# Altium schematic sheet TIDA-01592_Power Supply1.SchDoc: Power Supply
size 431 x 279 mm; Date: Not shown in title block; ApprovedBy: Not shown in title block; CheckedBy: Not shown in title block; Author: Not shown in title block; CompanyName: Not shown in title block; DrawnBy: Abhishek Vishwa; Engineer: Abhishek Vishwa; Organization: Not shown in title block; Address1: Not shown in title block; Address2: Not shown in title block; Address3: Not shown in title block; Address4: Not shown in title block; DocumentNumber: 1; Revision: Use project parameter SCH_Rev; SheetNumber: 2; SheetTotal: 5; PageSetup: Record=PageOptions¦CenterHorizontal=True¦CenterVertical=True¦PrintScale=1.00¦XCorrection=1.00¦YCorrection=1.00¦PrintKind=0¦BorderSize=5000000¦LeftOffset=0¦BottomOffset=0¦Orientation=2¦PaperLength=1000¦PaperWidth=1000¦Scale=100¦PaperSource=15¦PrintQuality=600¦MediaType=1¦DitherType=10¦PaperKind=Letter¦PrintScaleMode=1
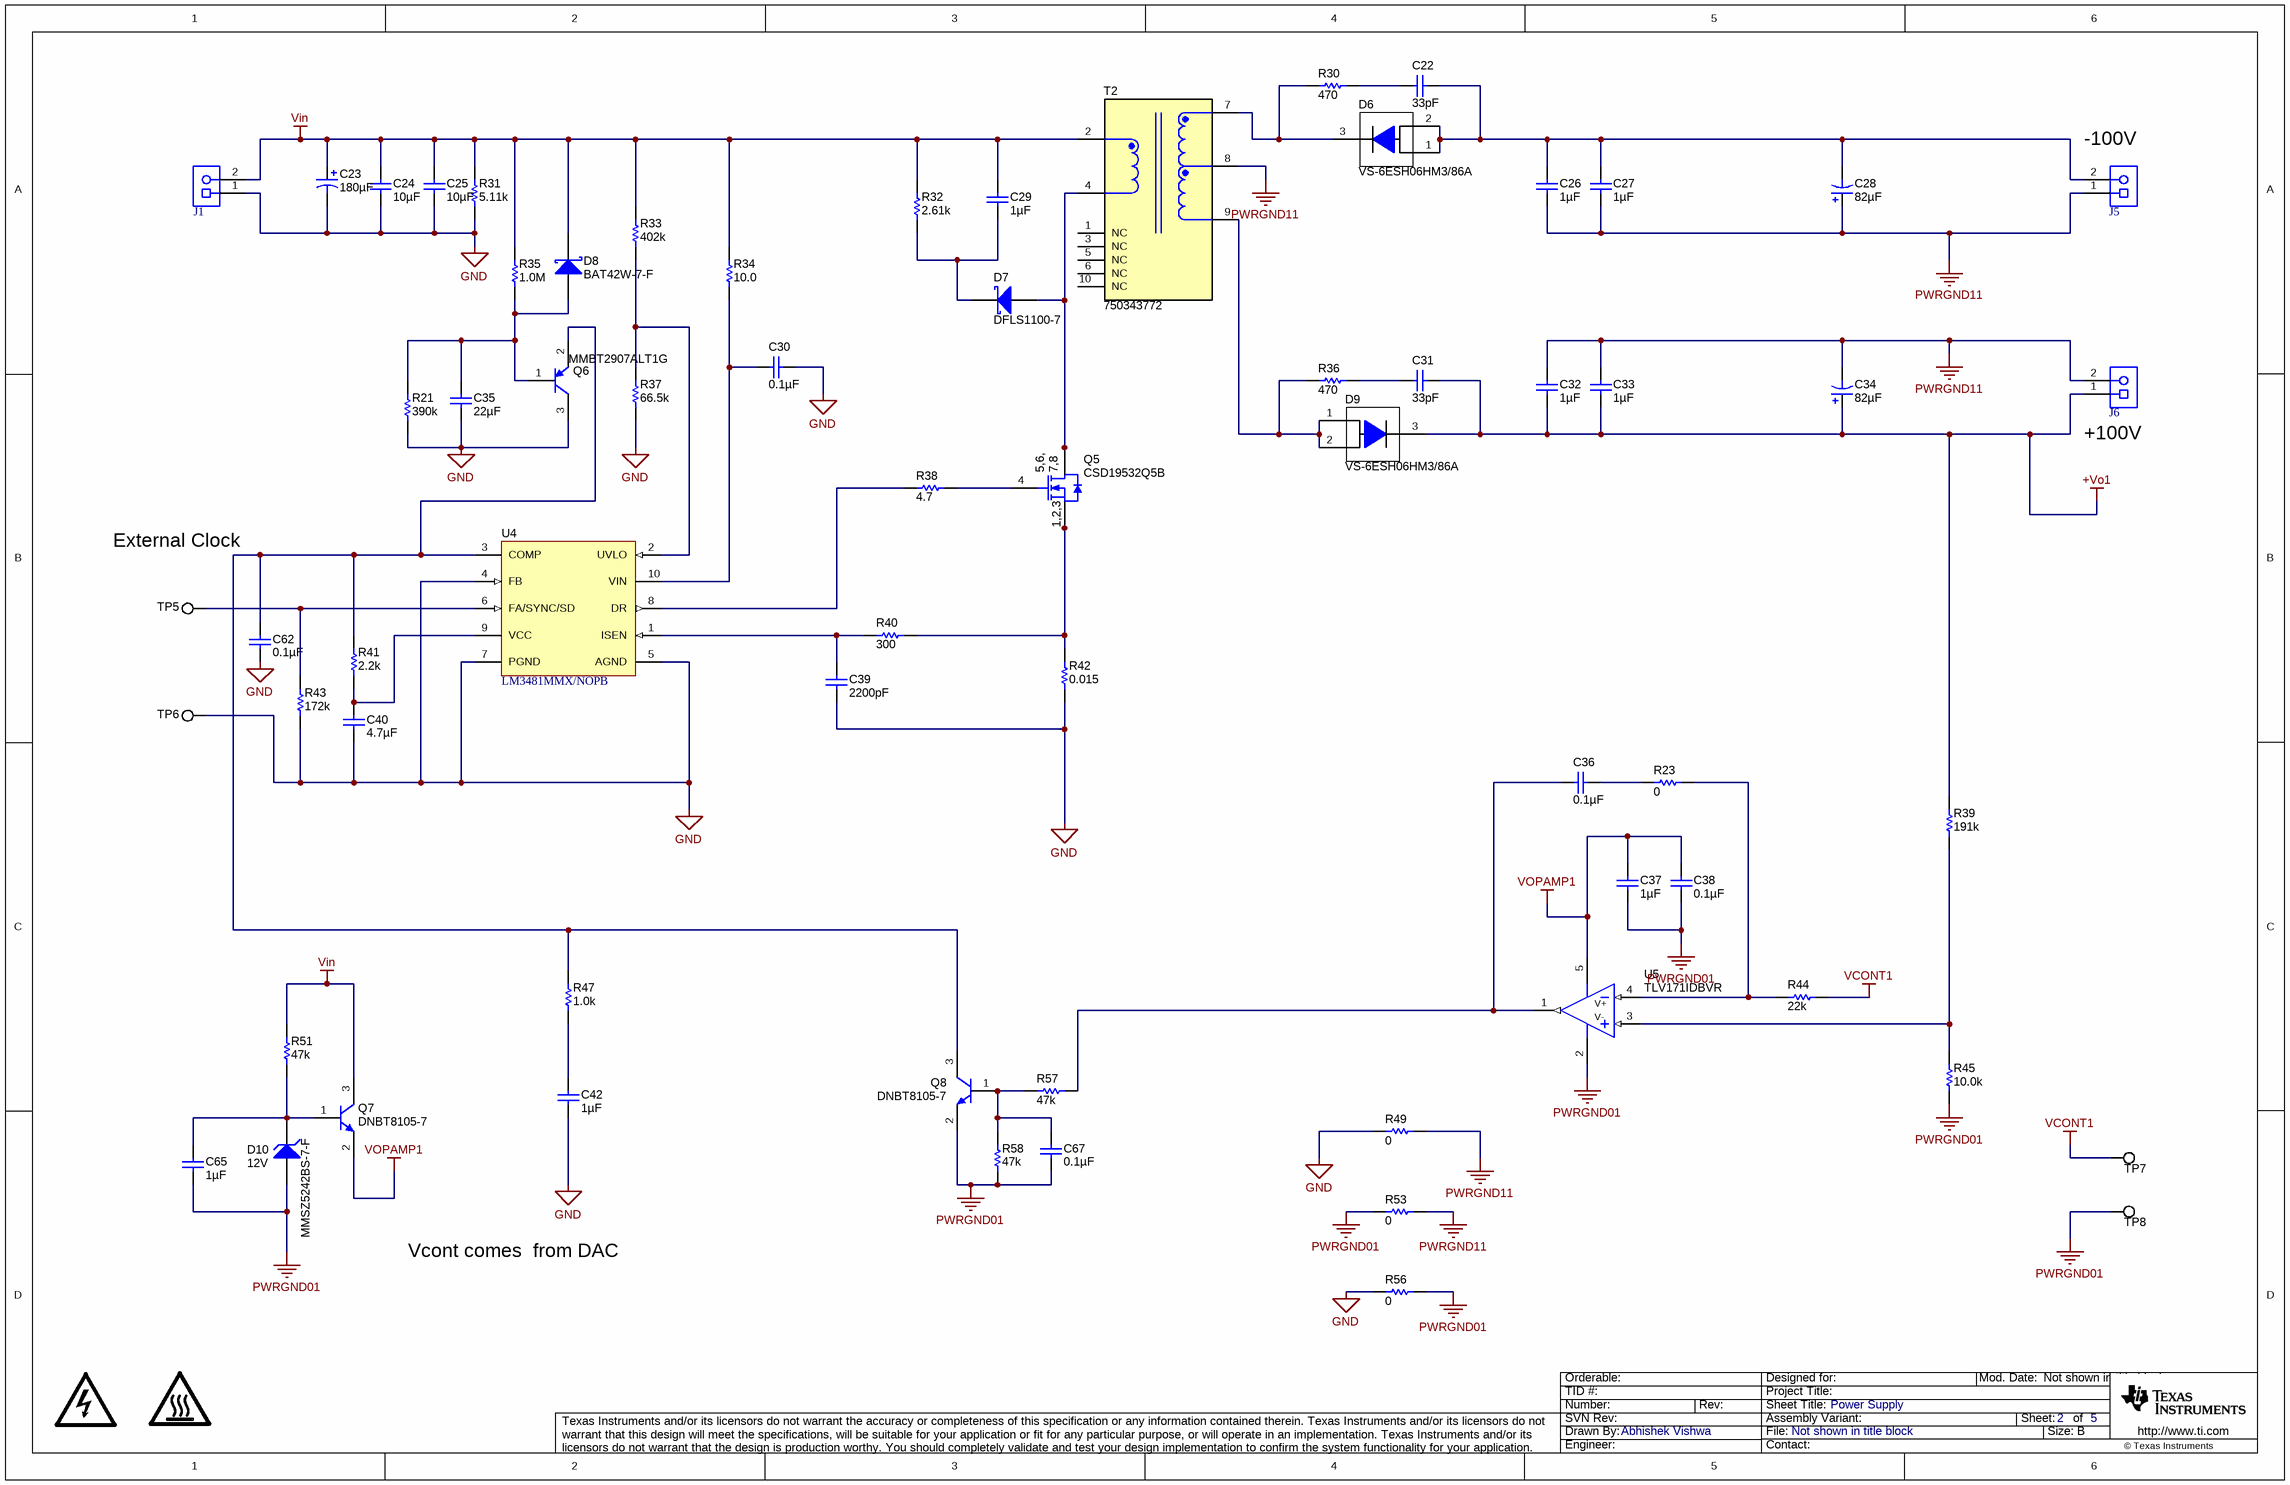
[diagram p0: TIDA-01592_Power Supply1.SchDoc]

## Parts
C22  ValueDisplayed: 33pF  [1206]  (hidden comment: 12067A330JAT2A)
C23  ValueDisplayed: 180µF  [FC_630x1120]  (hidden comment: 35TXW180MEFC6.3X25)
C24  ValueDisplayed: 10µF  [1206_180]  (hidden comment: GRM31CR61H106KA12L)
C25  ValueDisplayed: 10µF  [1206_180]  (hidden comment: GRM31CR61H106KA12L)
C26  ValueDisplayed: 1µF  [1812_180]  (hidden comment: C4532X7T2E105M250KE)
C27  ValueDisplayed: 1µF  [1812_180]  (hidden comment: C4532X7T2E105M250KE)
C28  ValueDisplayed: 82µF  [NHG_1000x2000]  (hidden comment: UCY2C820MPD9)
C29  ValueDisplayed: 1µF  [1206_180]  (hidden comment: GRM31CR72A105KA01L)
C30  ValueDisplayed: 0.1µF  [0603]  (hidden comment: GRM188R71H104KA93D)
C31  ValueDisplayed: 33pF  [1206]  (hidden comment: 12067A330JAT2A)
C32  ValueDisplayed: 1µF  [1812_180]  (hidden comment: C4532X7T2E105M250KE)
C33  ValueDisplayed: 1µF  [1812_180]  (hidden comment: C4532X7T2E105M250KE)
C34  ValueDisplayed: 82µF  [NHG_1000x2000]  (hidden comment: UCY2C820MPD9)
C35  ValueDisplayed: 22µF  [0805_HV1]  (hidden comment: C2012X5R1V226M125AC)
C36  ValueDisplayed: 0.1µF  [0603]  (hidden comment: GRM188R71H104KA93D)
C37  ValueDisplayed: 1µF  [0603]  (hidden comment: UMK107AB7105KA-T)
C38  ValueDisplayed: 0.1µF  [0603]  (hidden comment: GRM188R71H104KA93D)
C39  ValueDisplayed: 2200pF  [0402]  (hidden comment: GRM155R61H222KA01D)
C40  ValueDisplayed: 4.7µF  [0603]  (hidden comment: 0603ZD475KAT2A)
C42  ValueDisplayed: 1µF  [0603]  (hidden comment: C0603C105K3RACTU)
C62  ValueDisplayed: 0.1µF  [0603]  (hidden comment: GRM188R71H104KA93D)
C65  ValueDisplayed: 1µF  [0603]  (hidden comment: C0603C105K3RACTU)
C67  ValueDisplayed: 0.1µF  [0603]  (hidden comment: GRM188R71H104KA93D)
D6  VS-6ESH06HM3/86A  [TO-277A]
D7  DFLS1100-7  [PowerDI123]
D8  BAT42W-7-F  [SOD-123]
D9  VS-6ESH06HM3/86A  [TO-277A]
D10  MMSZ5242BS-7-F  value 12V  [SOD-323]
J1  1727010  [PhoenixConact_1727010]  (value not drawn)
J5  1727010  [PhoenixConact_1727010]  (value not drawn)
J6  1727010  [PhoenixConact_1727010]  (value not drawn)
LOGO2  CAUTION HOT SURFACE  [IEC_HotSurface_Small]  (value not drawn)  (graphical)
LOGO8  DANGER HIGH VOLTAGE  [IEC_HighVoltage_Small]  (value not drawn)  (graphical)
Q5  CSD19532Q5B  [DNK0008A]
Q6  MMBT2907ALT1G  [SOT-23]
Q7  DNBT8105-7  [SOT-23]
Q8  DNBT8105-7  [SOT-23]
R21  ValueDisplayed: 390k  [0603]  (hidden comment: CRCW0603390KJNEA)
R23  ValueDisplayed: 0  [0402]  (hidden comment: CRCW04020000Z0ED)
R30  ValueDisplayed: 470  [1206]  (hidden comment: CRCW1206470RJNEA)
R31  ValueDisplayed: 5.11k  [TNPW0603]  (hidden comment: TNPW06035K11BEEA)
R32  ValueDisplayed: 2.61k  [2010]  (hidden comment: CRCW20102K61FKEF)
R33  ValueDisplayed: 402k  [0603]  (hidden comment: CRCW0603402KFKEA)
R34  R4: 10.0  [0603]  (hidden comment: CRCW060310R0FKEAHP)
R35  ValueDisplayed: 1.0M  [0603]  (hidden comment: CRCW06031M00JNEA)
R36  ValueDisplayed: 470  [1206]  (hidden comment: CRCW1206470RJNEA)
R37  ValueDisplayed: 66.5k  [0603]  (hidden comment: CRCW060366K5FKEA)
R38  ValueDisplayed: 4.7  [0603]  (hidden comment: CRCW06034R70JNEA)
R39  ValueDisplayed: 191k  [0603]  (hidden comment: CRCW0603191KFKEA)
R40  ValueDisplayed: 300  [0603]  (hidden comment: CRCW0603300RJNEA)
R41  ValueDisplayed: 2.2k  [0603]  (hidden comment: ERJ-3GEYJ222V)
R42  ValueDisplayed: 0.015  [2010]  (hidden comment: WSL2010R0150FEA18)
R43  ValueDisplayed: 172k  [0603]  (hidden comment: RT0603DRE07172KL)
R44  ValueDisplayed: 22k  [0603]  (hidden comment: CRCW060322K0JNEA)
R45  ValueDisplayed: 10.0k  [0603]  (hidden comment: CRCW060310K0FKEA)
R47  ValueDisplayed: 1.0k  [0603]  (hidden comment: CRCW06031K00JNEA)
R49  ValueDisplayed: 0  [2010L]  (hidden comment: CRCW20100000Z0EF)
R51  ValueDisplayed: 47k  [1206]  (hidden comment: CRCW120647K0JNEA)
R53  ValueDisplayed: 0  [2010L]  (hidden comment: CRCW20100000Z0EF)
R56  ValueDisplayed: 0  [2010L]  (hidden comment: CRCW20100000Z0EF)
R57  ValueDisplayed: 47k  [0603]  (hidden comment: RC0603JR-0747KL)
R58  ValueDisplayed: 47k  [0603]  (hidden comment: RC0603JR-0747KL)
T2  750343772  [Wurth_EE16_7_5_5278]
TP5  5002  [Keystone5002]  (value not drawn)
TP6  5002  [Keystone5002]  (value not drawn)
TP7  5002  [Keystone5002]  (value not drawn)
TP8  5002  [Keystone5002]  (value not drawn)
U4  LM3481MMX/NOPB  [MUB10A_N]
U5  TLV171IDBVR  [DBV0005A_N]

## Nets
+Vo1: C31.1 C32.2 C33.2 C34.1(+) D9.3(K) J6.1 R39.2
GND: C23.2(-) C24.2 C25.2 C30.1 C35.2 C39.2 C40.2 C42.2 C62.1 J1.1 Q6.3(C) R21.1 R31.1 R37.1 R42.1 R43.1 R49.1 R56.1 TP6.1 U4.4(FB) U4.5(AGND) U4.7(PGND)
PWRGND01: C37.2 C38.2 C65.2 C67.1 D10.2(A) Q8.2(E) R45.2 R53.1 R56.2 R58.2 TP8.1 U5.2(V-)
PWRGND11: C26.2 C27.2 C28.1(+) C32.1 C33.1 C34.2(-) J5.1 J6.2 R49.2 R53.2 T2.8
VCONT1: R44.2 TP7.1
Vin: C23.1(+) C24.1 C25.1 C29.1 D8.1(K) J1.2 Q7.3(C) R31.2 R32.2 R33.2 R34.1 R35.2 R51.2 T2.2
VOPAMP1: C37.1 C38.1 Q7.2(E) U5.5(V+)
NetC22_1: C22.1 C26.1 C27.1 C28.2(-) D6.1(A) D6.2(A) J5.2
NetC22_2: C22.2 R30.2
NetC29_2: C29.2 D7.1(K) R32.1
NetC30_2: C30.2 R34.2 U4.10(VIN)
NetC31_2: C31.2 R36.2
NetC35_1: C35.1 D8.2(A) Q6.1(B) R21.2 R35.1
NetC36_1: C36.1 R57.1 U5.1(OUT)
NetC36_2: C36.2 R23.1
NetC39_1: C39.1 R40.1 U4.1(ISEN)
NetC40_1: C40.1 R41.2 U4.9(VCC)
NetC42_1: C42.1 R47.1
NetC62_2: C62.2 Q6.2(E) Q8.3(C) R41.1 R47.2 U4.3(COMP)
NetC65_1: C65.1 D10.1(K) Q7.1(B) R51.1
NetC67_2: C67.2 Q8.1(B) R57.2 R58.1
NetD6_3: D6.3(K) R30.1 T2.7
NetD7_2: D7.2(A) Q5.5(D) Q5.6(D) Q5.7(D) Q5.8(D) Q5.9(D) T2.4
NetD9_1: D9.1(A) D9.2(A) R36.1 T2.9
NetQ5_1: Q5.1(S) Q5.2(S) Q5.3(S) R40.2 R42.2
NetQ5_4: Q5.4(G) R38.2
NetR23_2: R23.2 R44.1 U5.4(IN-)
NetR33_1: R33.1 R37.2 U4.2(UVLO)
NetR38_1: R38.1 U4.8(DR)
NetR39_1: R39.1 R45.1 U5.3(IN+)
NetR43_2: R43.2 TP5.1 U4.6(FA/SYNC/SD)

Not connected (* = marked no-connect by the designer): T2 1(NC) 3(NC) 5(NC) 6(NC) 10(NC)

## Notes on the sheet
- (near J5) -100V
- (near J6) +100V
- External Clock Synchronization
- Vcont comes  from DAC

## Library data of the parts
C22 C31 = 12067A330JAT2A: CAP, CERM, 33 pF, 500 V,+/- 5%, C0G/NP0, 1206; Manufacturer: AVX; Polarized: N; CompType: Capacitor; Value: 33pF; U/M: EA; Cap_F: 0.000000000033; Tolerance_%: 5; VDC_V: 500; Value2: 500V; TaMin_C: -55; TaMax_C: 125; SizeArea_mm2: 5.12; SizeAreaWB_mm2: 10.92; SizeX_mm: 3.2; SizeY_mm: 1.6; SizeZ_mm: 1.35; AEC Category: Q200; Green_Lifecycle: Not Set; Green_REACh: Incomplete
C23 = EEU-FC1V470: CAP, AL, 180 µF, 35 V, +/- 20%, TH; Manufacturer: Rubycon; Polarized: Y; CompType: Capacitor; Value: 180uF; U/M: EA; Cap_F: 0.000180; Tolerance_%: 20; VDC_V: 35; Value2: 35V; IRMS_A: 0.29; TaMin_C: -55; TaMax_C: 105; Cap_Case: 6.3x11.2mm; SizeAreaWB_mm2: 68.89; SizeArea_mm2: 39.69; SizeX_mm: 6.3; SizeZ_mm: 12.2; AEC Category: Q200; AEC Grade: 2
C24 C25 = GRM31CR61H106KA12L: CAP, CERM, 10 µF, 50 V,+/- 10%, X5R, 1206; Manufacturer: MuRata; Polarized: N; CompType: Capacitor; Value: 10uF; U/M: EA; Cap_F: 0.00001; Tolerance_%: 10; VDC_V: 50; Value2: 50V; TaMin_C: -55; TaMax_C: 85; Cap_Case: 1206; SizeArea_mm2: 5.12; SizeAreaWB_mm2: 10.92; SizeX_mm: 3.2; SizeY_mm: 1.6; SizeZ_mm: 1.8; AEC Category: Q200; Green_Lifecycle: Active; Green_REACh: Passed
C26 C27 C32 C33 = C4532X7R1H105K160KA: CAP, CERM, 1 µF, 250 V,+/- 20%, X7T, 1812; Manufacturer: TDK Corporation; Polarized: N; CompType: Capacitor; Value: 1uF; U/M: EA; Cap_F: 0.000001; Tolerance_%: 20; ESR_ohm: 0.007217; Value1: 0.007217 ohm; VDC_V: 50; Value2: 250V; IRMS_A: 2.85919; TaMin_C: -55; TaMax_C: 125; Cap_Case: 1812; SizeArea_mm2: 14.4; SizeAreaWB_mm2: 23.1; SizeX_mm: 4.5; SizeY_mm: 3.2; SizeZ_mm: 1.8; AEC Category: Q200
C28 C34 = ECA-2AHG101: CAP, AL, 82 µF, 160 V, +/- 20%, TH; Manufacturer: Nichicon; Polarized: Y; CompType: Capacitor; Value: 82uF; U/M: EA; Cap_F: 0.0001; Tolerance_%: 20; VDC_V: 160; Value2: 160V; IRMS_A: 0.265; TaMin_C: -55; TaMax_C: 105; Cap_Case: 10x20mm; SizeAreaWB_mm2: 144; SizeArea_mm2: 100; SizeX_mm: 10; SizeZ_mm: 22; AEC Category: Q200; Green_Lifecycle: Active; Green_REACh: Passed
C29 = GRM31CR72A105KA01L: CAP, CERM, 1 µF, 100 V,+/- 10%, X7R, 1206; Manufacturer: MuRata; Polarized: N; CompType: Capacitor; Value: 1uF; U/M: EA; Cap_F: 0.000001; Tolerance_%: 10; VDC_V: 100; Value2: 100V; TaMin_C: -55; TaMax_C: 125; Cap_Case: 1206; SizeArea_mm2: 5.12; SizeAreaWB_mm2: 10.92; SizeX_mm: 3.2; SizeY_mm: 1.6; SizeZ_mm: 1.8; AEC Category: Q200; Green_Lifecycle: Active; Green_REACh: Passed
C30 C36 C38 C62 C67 = GRM188R71H104KA93D: CAP, CERM, 0.1 µF, 50 V,+/- 10%, X7R, 0603; Manufacturer: MuRata; Polarized: N; CompType: Capacitor; Value: 0.1uF; U/M: EA; Cap_F: 0.0000001; Tolerance_%: 10; VDC_V: 50; Value2: 50V; TaMin_C: -55; TaMax_C: 125; SizeArea_mm2: 1.28; SizeAreaWB_mm2: 4.68; SizeX_mm: 1.6; SizeY_mm: 0.8; SizeZ_mm: 1; AEC Category: Q200; Green_Lifecycle: Active; Green_REACh: Passed
C35 = GRM21BC81C226ME44L: CAP, CERM, 22 µF, 35 V,+/- 20%, X5R, 0805; Manufacturer: TDK Corporation; Polarized: N; CompType: Capacitor; Value: 22uF; U/M: EA; Cap_F: 0.000022; Tolerance_%: 20; VDC_V: 16; Value2: 35V; TempCo: X6S; TaMin_C: -55; TaMax_C: 105; Cap_Case: 0805; SizeArea_mm2: 2.5; SizeAreaWB_mm2: 6.75; SizeX_mm: 2; SizeY_mm: 1.25; SizeZ_mm: 1.45; AEC Category: Q200
C37 = UMK107AB7105KA-T: CAP, CERM, 1 µF, 50 V,+/- 10%, X7R, 0603; Manufacturer: Taiyo Yuden; Polarized: N; CompType: Capacitor; Value: 1uF; U/M: EA; Cap_F: 0.000001; Tolerance_%: 10; VDC_V: 50; Value2: 50V; TaMin_C: -55; TaMax_C: 125; SizeArea_mm2: 1.28; SizeAreaWB_mm2: 4.68; SizeX_mm: 1.6; SizeY_mm: 0.8; SizeZ_mm: 1; AEC Category: Q200; Green_Lifecycle: Active; Green_REACh: Passed
C39 = GRM155R61H222KA01D: CAP, CERM, 2200 pF, 50 V,+/- 10%, X5R, 0402; Manufacturer: MuRata; Polarized: N; CompType: Capacitor; Value: 2200pF; U/M: EA; Cap_F: 0.0000000022; Tolerance_%: 10; VDC_V: 50; Value2: 50V; TaMin_C: -55; TaMax_C: 85; SizeArea_mm2: 0.5; SizeAreaWB_mm2: 3; SizeX_mm: 1; SizeZ_mm: 0.6; AEC Category: Q200; Green_Lifecycle: Active; Green_REACh: Passed
C40 = 0603ZD475KAT2A: CAP, CERM, 4.7 µF, 10 V,+/- 10%, X5R, 0603; Manufacturer: AVX; Polarized: N; CompType: Capacitor; Value: 4.7uF; U/M: EA; Cap_F: 0.0000047; Tolerance_%: 10; Value2: 10V; TaMin_C: -55; TaMax_C: 85; SizeArea_mm2: 1.28; SizeAreaWB_mm2: 4.68; SizeX_mm: 1.6; SizeY_mm: 0.8; SizeZ_mm: 1; AEC Category: Q200; Green_Lifecycle: Active; Green_REACh: Passed
C42 C65 = C0603C105K3RACTU: CAP, CERM, 1 µF, 25 V,+/- 10%, X7R, 0603; Manufacturer: Kemet; Polarized: N; CompType: Capacitor; Value: 1uF; U/M: EA; Cap_F: 0.000001; Tolerance_%: 10; VDC_V: 25; Value2: 25V; TaMin_C: -55; TaMax_C: 125; SizeArea_mm2: 1.28; SizeAreaWB_mm2: 4.68; SizeX_mm: 1.6; SizeY_mm: 0.8; SizeZ_mm: 1; AEC Category: Q200; Green_Lifecycle: Active; Green_REACh: Passed
D6 D9 = VS-6ESH06HM3/86A: Diode, Hyperfast, 600 V, 6 A, AEC-Q101, TO-277A; Manufacturer: Vishay-Semiconductor; SymbolCreator: a0412235; U/M: EA; Vf_V: 1.05; Value: 600V; Value1: 6A; Value2: 1.05V; Io_A: 6; Vr_V: 600; TJmax_C: 175; RJC_CperW: 3.5; SizeAreaWB_mm2: 57.375; SizeArea_mm2: 30.875; SizeX_mm: 6.5; SizeY_mm: 4.75; SizeZ_mm: 1.2; AEC Category: Q101; AEC Qualified: Y
D7 = DFLS1100-7: Diode, Schottky, 100 V, 1 A, PowerDI123; Manufacturer: Diodes Inc.; U/M: EA; Vf_V: 0.77; Value: 100V; Value1: 1A; Value2: 0.77V; Io_A: 1; Vr_V: 100; TJmax_C: 175; RJC_CperW: 7; SizeAreaWB_mm2: 13.066; SizeArea_mm2: 6.586; SizeX_mm: 3.7; SizeY_mm: 1.78; SizeZ_mm: 0.98; AEC Category: Q101; Green_Lifecycle: Active; Green_REACh: Passed
D8 = BAT42W-7-F: Diode, Schottky, 30 V, 0.2 A, SOD-123; Manufacturer: Diodes Inc.; U/M: EA; Vf_V: 1; Value: 30V; Value1: 0.2A; Value2: 1V; Io_A: 0.2; Vr_V: 30; SizeAreaWB_mm2: 13.095; SizeArea_mm2: 6.545; SizeX_mm: 3.85; SizeY_mm: 1.7; SizeZ_mm: 1.35; AEC Category: Q101; Green_Lifecycle: Not Set; Green_REACh: Incomplete
D10 = MMSZ5242BS-7-F: Diode, Zener, 12 V, 200 mW, SOD-323; Manufacturer: Diodes Inc.; SymbolCreator: a0412235; U/M: EA; Power_W: 0.2; Vz_V: 12; Value1: 0.2W; RJA_CperW: 350; SizeAreaWB_mm2: 8.695; SizeArea_mm2: 3.645; SizeX_mm: 2.7; SizeY_mm: 1.35; SizeZ_mm: 1; AEC Category: Q101
J1 J5 J6 = 1727010: Conn Term Block, 2POS, 3.81mm, TH; Manufacturer: Phoenix Contact; SymbolCreator: a0412235; CompType: Terminal Block
LOGO2 = IEC_HotSurface: IEC 61010-1 Hot Surface Warning; SymbolCreator: a0412235
LOGO8 = IEC_HighVoltage: IEC 61010-1 High Voltage Warning; SymbolCreator: a0412235
Q5 = CSD19532Q5B: MOSFET, N-CH, 100 V, 17 A, DNK0008A (VSON-CLIP-8); Manufacturer: Texas Instruments; Alternate Manufacturer: None; U/M: EA; ChType: N; Value: 100V; VdsMax_V: 100; Value1: ? ohm; Value2: 48 nC; QgTyp_nC: 48; Vgs_V: 20; IdsMax_A: 17; SizeAreaWB_mm2: 56; SizeArea_mm2: 30; SizeX_mm: 6; SizeY_mm: 5; SizeZ_mm: 1; AEC Category: Q101
Q6 = MMBT2907ALT1G, ON Semiconductor: Transistor, PNP, 60 V, 0.6 A, SOT-23; CompType: BJT; PNP: 1; NPN: 0; Vceo_V: 60; Vcesat1_V: 1.6; Value: 60 V; IcRated_A: 0.6; Value1: 0.6 A; TaMin_C: -55; TaMax_C: 150; SizeAreaWB_mm2: 14; SizeArea_mm2: 7.5; SizeX_mm: 2.5; SizeY_mm: 3; SizeZ_mm: 1.1; U/M: EA; AEC Category: Q101; Green_Lifecycle: Active; Green_REACh: Passed
Q7 Q8 = DNBT8105-7, Diodes Inc.: Transistor, NPN, 60 V, 1 A, AEC-Q101, SOT-23; CompType: BJT; PNP: 0; NPN: 1; Vceo_V: 60; Vcesat1_V: 0.25; Value: 60 V; Value1: 1 A; HfeMax: 300; TaMin_C: -55; TaMax_C: 150; SizeAreaWB_mm2: 14; SizeArea_mm2: 7.5; SizeX_mm: 2.5; SizeY_mm: 3; SizeZ_mm: 1.1; U/M: EA; AEC Category: Q101; AEC Qualified: Y; Green_Lifecycle: Not Set; Green_REACh: Incomplete
R21 = CRCW0603390KJNEA: RES, 390 k, 5%, 0.1 W, 0603; Manufacturer: Vishay-Dale; CompType: Resistor; Value: 390k; Res_ohm: 390000; Tolerance_%: 5; Power_W: 0.1; Value2: 0.1W; VDC_V: 75; TempCo: 200 ppm/C; SizeArea_mm2: 1.28; SizeX_mm: 1.6; SizeY_mm: 0.8; SizeZ_mm: 1; EIA_Code: E24; U/M: EA; AEC Category: Q200
R23 = CRCW04020000Z0ED: RES, 0, 5%, 0.063 W, 0402; Manufacturer: Vishay-Dale; CompType: Resistor; Value: 0; Value_Code: 0000; Tolerance_%: 5; Power_W: 0.063; Value2: 0.063W; VDC_V: 50; TempCo: 200 ppm/C; SizeArea_mm2: 0.5; SizeX_mm: 1; SizeZ_mm: 0.6; EIA_Code: E24; U/M: EA; AEC Category: Q200; Green_Lifecycle: Active; Green_REACh: Passed
R30 R36 = CRCW1206470RJNEA: RES, 470, 5%, 0.25 W, 1206; Manufacturer: Vishay-Dale; CompType: Resistor; Value: 470; Value_Code: 470R; Tolerance_%: 5; Power_W: 0.25; Value2: 0.25W; VDC_V: 200; TempCo: 200 ppm/C; SizeArea_mm2: 5.12; SizeX_mm: 3.2; SizeY_mm: 1.6; SizeZ_mm: 1.35; EIA_Code: E24; U/M: EA; AEC Category: Q200
R31 = TNPW06035K11BEEA: RES, 5.11 k, 0.1%, 0.1 W, AEC-Q200 Grade 1, 0603; Manufacturer: Vishay-Dale; CompType: Resistor; Value: 5.11k; Res_ohm: 5110; Value_Code: 5k11; Tolerance_%: 0.1; Value2: 0.1W; VDC_V: 75; TempCo: 25 ppm/C; SizeArea_mm2: 1.36; SizeX_mm: 1.6; SizeY_mm: 0.85; SizeZ_mm: 0.55; EIA_Code: E192; U/M: EA; AEC Category: Q200; AEC Qualified: Y; AEC Grade: 1
R32 = CRCW20102K61FKEF: RES, 2.61 k, 1%, 0.75 W, AEC-Q200 Grade 0, 2010; Manufacturer: Vishay-Dale; CompType: Resistor; Value: 2.61k; Res_ohm: 2610; Value_Code: 2k61; Tolerance_%: 1; Power_W: 0.75; Value2: 0.75W; VDC_V: 400; TempCo: 100 ppm/C; SizeArea_mm2: 12.5; SizeX_mm: 5; SizeY_mm: 2.5; SizeZ_mm: 1.66; EIA_Code: E96; U/M: EA; AEC Category: Q200; AEC Qualified: Y; AEC Grade: 0
R33 = CRCW0603402KFKEA: RES, 402 k, 1%, 0.1 W, 0603; Manufacturer: Vishay-Dale; CompType: Resistor; Value: 402k; Res_ohm: 402000; Tolerance_%: 1; Power_W: 0.1; Value2: 0.1W; VDC_V: 75; TempCo: 100 ppm/C; SizeArea_mm2: 1.28; SizeX_mm: 1.6; SizeY_mm: 0.8; EIA_Code: E96; U/M: EA; AEC Category: Q200; Green_Lifecycle: Active; Green_REACh: Passed
R34 = CRCW060310R0FKEAHP: RES, 10.0, 1%, 0.25 W, 0603; Manufacturer: Vishay-Dale; CompType: Resistor; Value: 10.0; Res_ohm: 10; Value_Code: 10R0; Tolerance_%: 1; Power_W: 0.25; Value2: 0.25W; VDC_V: 75; TempCo: 100 ppm/C; SizeArea_mm2: 1.28; SizeX_mm: 1.6; SizeY_mm: 0.8; EIA_Code: E96; U/M: EA; AEC Category: Q200; Green_Lifecycle: Active; Green_REACh: Passed
R35 = CRCW06031M00JNEA: RES, 1.0 M, 5%, 0.1 W, 0603; Manufacturer: Vishay-Dale; CompType: Resistor; Value: 1.0Meg; Res_ohm: 1000000; Value_Code: 1M00; Tolerance_%: 5; Power_W: 0.1; Value2: 0.1W; VDC_V: 75; TempCo: 200 ppm/C; SizeArea_mm2: 1.28; SizeX_mm: 1.6; SizeY_mm: 0.8; SizeZ_mm: 1; EIA_Code: E24; U/M: EA; AEC Category: Q200; Green_Lifecycle: Active; Green_REACh: Passed
R37 = CRCW060366K5FKEA: RES, 66.5 k, 1%, 0.1 W, 0603; Manufacturer: Vishay-Dale; CompType: Resistor; Value: 66.5k; Res_ohm: 66500; Value_Code: 66k5; Tolerance_%: 1; Power_W: 0.1; Value2: 0.1W; VDC_V: 75; TempCo: 100 ppm/C; SizeArea_mm2: 1.28; SizeX_mm: 1.6; SizeY_mm: 0.8; EIA_Code: E96; U/M: EA; AEC Category: Q200; Green_Lifecycle: Active; Green_REACh: Passed
R38 = CRCW06034R70JNEA: RES, 4.7, 5%, 0.1 W, 0603; Manufacturer: Vishay-Dale; CompType: Resistor; Value: 4.7; Value_Code: 4R70; Tolerance_%: 5; Power_W: 0.1; Value2: 0.1W; VDC_V: 75; TempCo: 200 ppm/C; SizeArea_mm2: 1.28; SizeX_mm: 1.6; SizeY_mm: 0.8; SizeZ_mm: 1; EIA_Code: E24; U/M: EA; AEC Category: Q200; Green_Lifecycle: Active; Green_REACh: Passed
R39 = CRCW0603191KFKEA: RES, 191 k, 1%, 0.1 W, 0603; Manufacturer: Vishay-Dale; CompType: Resistor; Value: 191k; Res_ohm: 191000; Tolerance_%: 1; Power_W: 0.1; Value2: 0.1W; VDC_V: 75; TempCo: 100 ppm/C; SizeArea_mm2: 1.28; SizeX_mm: 1.6; SizeY_mm: 0.8; EIA_Code: E96; U/M: EA; AEC Category: Q200; Green_Lifecycle: Active; Green_REACh: Passed
R40 = CRCW0603300RJNEA: RES, 300, 5%, 0.1 W, 0603; Manufacturer: Vishay-Dale; CompType: Resistor; Value: 300; Value_Code: 300R; Tolerance_%: 5; Power_W: 0.1; Value2: 0.1W; VDC_V: 75; TempCo: 200 ppm/C; SizeArea_mm2: 1.28; SizeX_mm: 1.6; SizeY_mm: 0.8; SizeZ_mm: 1; EIA_Code: E24; U/M: EA; AEC Category: Q200; Green_Lifecycle: Active; Green_REACh: Passed
R41 = ERJ-3GEYJ222V: RES, 2.2 k, 5%, 0.1 W, AEC-Q200 Grade 0, 0603; Manufacturer: Panasonic; CompType: Resistor; Value: 2.2k; Res_ohm: 2200; Value_Code: 2k20; Tolerance_%: 5; Power_W: 0.1; Value2: 0.1W; VDC_V: 75; TempCo: 200 ppm/C; SizeArea_mm2: 1.28; SizeX_mm: 1.6; SizeY_mm: 0.8; SizeZ_mm: 1; EIA_Code: E24; U/M: EA; AEC Category: Q200; AEC Qualified: Y; AEC Grade: 0; Green_Lifecycle: Active; Green_REACh: Passed
R42 = WSL2010R0150FEA18: RES, 0.015, 1%, 1 W, 2010; Manufacturer: Vishay-Dale; CompType: Resistor; Value: 0.015; Value_Code: R015; Tolerance_%: 1; Value2: 1W; TempCo: 75 ppm/C; SizeArea_mm2: 12.5; SizeX_mm: 5; SizeY_mm: 2.5; SizeZ_mm: 1.66; EIA_Code: E96; U/M: EA; AEC Category: Q200
R43 = RT0603DRE07172KL: RES, 172 k, 0.5%, 0.1 W, 0603; Manufacturer: Yageo America; CompType: Resistor; Value: 172k; Res_ohm: 172000; Tolerance_%: 0.5; Power_W: 0.1; Value2: 0.1W; VDC_V: 75; TempCo: 50 ppm/C; SizeArea_mm2: 1.28; SizeX_mm: 1.6; SizeY_mm: 0.8; SizeZ_mm: 1; EIA_Code: E192; U/M: EA; AEC Category: Q200
R44 = CRCW060322K0JNEA: RES, 22 k, 5%, 0.1 W, 0603; Manufacturer: Vishay-Dale; CompType: Resistor; Value: 22k; Res_ohm: 22000; Value_Code: 22k0; Tolerance_%: 5; Power_W: 0.1; Value2: 0.1W; VDC_V: 75; TempCo: 200 ppm/C; SizeArea_mm2: 1.28; SizeX_mm: 1.6; SizeY_mm: 0.8; SizeZ_mm: 1; EIA_Code: E24; U/M: EA; AEC Category: Q200; Green_Lifecycle: Active; Green_REACh: Passed
R45 = CRCW060310K0FKEA: RES, 10.0 k, 1%, 0.1 W, 0603; Manufacturer: Vishay-Dale; CompType: Resistor; Value: 10.0k; Res_ohm: 10000; Value_Code: 10k0; Tolerance_%: 1; Power_W: 0.1; Value2: 0.1W; VDC_V: 75; TempCo: 100 ppm/C; SizeArea_mm2: 1.28; SizeX_mm: 1.6; SizeY_mm: 0.8; EIA_Code: E96; U/M: EA; AEC Category: Q200; Green_Lifecycle: Active; Green_REACh: Passed
R47 = CRCW06031K00JNEA: RES, 1.0 k, 5%, 0.1 W, 0603; Manufacturer: Vishay-Dale; CompType: Resistor; Value: 1.0k; Res_ohm: 1000; Value_Code: 1k00; Tolerance_%: 5; Power_W: 0.1; Value2: 0.1W; VDC_V: 75; TempCo: 200 ppm/C; SizeArea_mm2: 1.28; SizeX_mm: 1.6; SizeY_mm: 0.8; SizeZ_mm: 1; EIA_Code: E24; U/M: EA; AEC Category: Q200; Green_Lifecycle: Active; Green_REACh: Passed
R49 R53 R56 = CRCW20100000Z0EF: RES, 0, 5%, 0.75 W, AEC-Q200 Grade 0, 2010; Manufacturer: Vishay-Dale; CompType: Resistor; Value: 0; Value_Code: 0000; Tolerance_%: 5; Power_W: 0.75; Value2: 0.75W; TempCo: ppm/C; SizeArea_mm2: 12.5; SizeY_mm: 2.5; SizeZ_mm: 1.66; EIA_Code: E24; U/M: EA; AEC Category: Q200; AEC Qualified: Y
R51 = CRCW120647K0JNEA: RES, 47 k, 5%, 0.25 W, 1206; Manufacturer: Vishay-Dale; CompType: Resistor; Value: 47k; Res_ohm: 47000; Value_Code: 47k0; Tolerance_%: 5; Power_W: 0.25; Value2: 0.25W; VDC_V: 200; TempCo: 200 ppm/C; SizeArea_mm2: 5.12; SizeX_mm: 3.2; SizeY_mm: 1.6; SizeZ_mm: 1.35; EIA_Code: E24; U/M: EA; AEC Category: Q200
R57 R58 = RC0603JR-0747KL: RES, 47 k, 5%, 0.1 W, 0603; Manufacturer: Yageo America; CompType: Resistor; Value: 47k; Res_ohm: 47000; Value_Code: 47k0; Tolerance_%: 5; Power_W: 0.1; Value2: 0.1W; VDC_V: 50; TempCo: 100 ppm/C; SizeArea_mm2: 1.28; SizeX_mm: 1.6; SizeY_mm: 0.8; SizeZ_mm: 1; EIA_Code: E24; U/M: EA; AEC Category: Q200; Green_Lifecycle: Active; Green_REACh: Passed
T2 = CMP-0081056-1: Transformer, 13 uH, TH; Manufacturer: Wurth Elektronik; LeakageInd_H: 300nH; Rsec2_ohm: 1.45; SizeAreaWB_mm2: 379.25; DCR_ohm: 0.022; Value: 13uH; Lp: 13; SizeZ_mm: 18.8; SizeX_mm: 16.5; SizeY_mm: 18.5; Ns1toNp: 5.5; SizeArea_mm2: 305.25; Ind_H: 13µH; AEC Qualified: N; Rsec1_ohm: 1; AEC Category: Q200
TP5-TP8 = 5002: Test Point, Miniature, White, TH; Manufacturer: Keystone; CompType: Test Point Loop; ContactFinish: Silver
U4 = LM3481MMX/NOPB: High Efficiency Low-Side N-Channel Controller for Switching Regulators, 10-pin MSOP, Pb-Free; Manufacturer: Texas Instruments; PackageTopMarking: ZXTT*SJPB; PowerWise: N; CompType: MiscPower
U5 = TLV171IDBVR: 36V, Low-Power, RRO, General-Purpose Operational Amplifier, DBV0005A (SOT-23-5); Alternate PartNumber: TLV171IDBVT; Manufacturer: Texas Instruments; SizeArea_mm2: 8.12; SizeAreaWB_mm2: 14.82; SizeX_mm: 2.8; SizeY_mm: 2.9; SizeZ_mm: 1.45; CompType: IC; U/M: EA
